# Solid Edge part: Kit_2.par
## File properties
Author: bmolnar
Last saved by: bmolnar
Revision: 78
Sűrűség: 0,000 kg/m^3
Pontosság: 0,990
Username: bmolnar
Dokumentum tartalom típus: 0
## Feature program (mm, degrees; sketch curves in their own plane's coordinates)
base feature "unnamed BaseFeature 1"
thread "unnamed Thread 1"
thread "unnamed Thread 2"
thread "unnamed Thread 3"
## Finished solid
Body 1: solid body, 300 faces, 731 edges, 450 vertices.
  Faces by surface: plane 146, cylinder 60, swept 55, cone 27, torus 11, spline 1
  Edges by curve: line 449, circle 159, spline 118, curve on surface 4, intersection 1
Bounding box of the edges (mm; curved faces can reach further): 49.000 x 49.000 x 14.100, from (-24.5, -24.5, 79.6) to (24.5, 24.5, 93.7).
Cylindrical faces by radius (mm): R0.2 x30, R0.335 x1, R0.5307 x1, R1.25 x1, R2.4585 x2, R3 x2, R3.75 x4, R4 x8, R4.283 x1, R4.5 x4, R6.27 x1, R6.85 x1, R7 x1, R8.16 x1, R8.25 x1, R10.6633 x1
Conical faces (half-angle, radius in mm at the cone's reference point): 0.5 deg R8 x4, 3 deg R8.205 x1, 7 deg R7.5925 x1, 14 deg R6.135 x1, 14 deg R6.4811 x1, 15 deg R3.067 x4, 15 deg R3.933 x4, 17 deg R6.135 x1, 23 deg R6.829 x1, 42.5 deg R6.1233 x1, 45 deg R2.8085 x4, 45 deg R7 x1, 84 deg R6.4608 x1, 85 deg R7.9463 x1, 87 deg R6.1765 x1
Toroidal faces (ring radius, tube radius in mm): R3.55 r0.2 x8, R6.8057 r0.2025 x1, R7.2522 r0.2925 x1, R7.96 r0.2 x1
Planar faces by outward normal: +x 12, +y 14, +z 17, -x 10, -y 14, -z 4, oblique 75
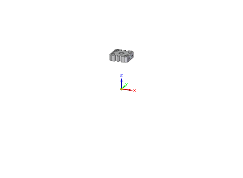
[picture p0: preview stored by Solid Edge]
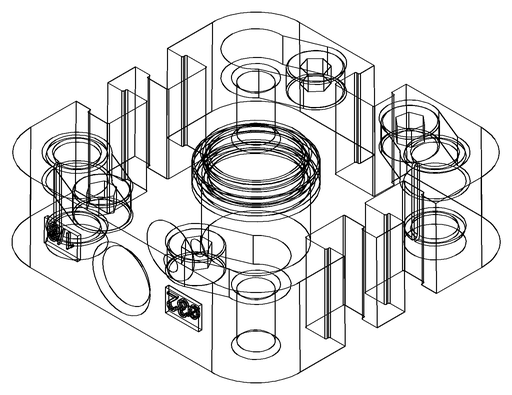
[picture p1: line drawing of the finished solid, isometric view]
